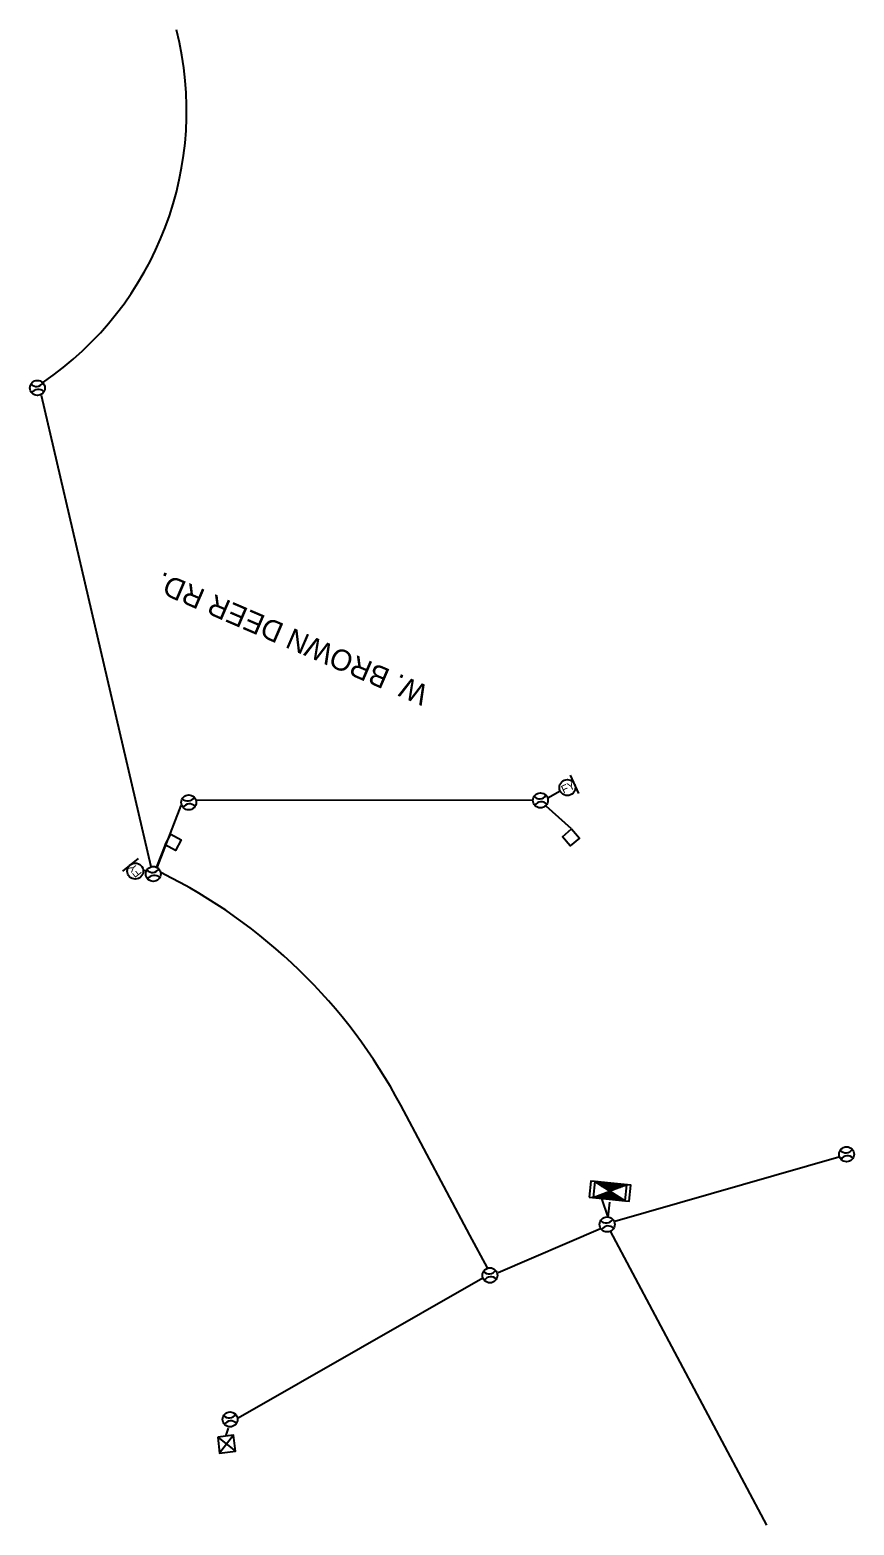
# Model space of a CAD drawing. Extents: x 601562 to 605316, y 332050 to 402250.
# Drawn here: x 603536 to 603948, y 349499 to 350247 of the extents above; entities that cross this region are included whole.
import ezdxf

# ---------------------------------------------------------------- set-up
doc = ezdxf.new("R2010")
doc.units = 0
doc.layers.add('P_FTMS', color=7, linetype='Continuous')
doc.layers.add('P_FTMSConduit', color=7, linetype='Continuous')

# ---------------------------------------------------------------- blocks, each defined once
blk = doc.blocks.new('FFY')
at = {"layer": 'P_FTMS'}
blk.add_line((24.4, -30.5), (24.4, 30.5), dxfattribs=at)
blk.add_circle((0, 0), 24.4, dxfattribs=at)
blk.add_text('FY', height=24.38, dxfattribs=at).set_placement((-18.5, -12.2))
blk = doc.blocks.new('FCB_2')
at = {"layer": 'P_FTMS'}
for p, q in [((-48.3, 24.1), (-48, 24.4)), ((-45.5, 22.7), (-47.1, 24.4)), ((-46.9, 23.4), (-46, 24.4)), ((-45.5, 22.8), (-43.9, 24.4)), ((-41.4, 20.7), (-45.1, 24.4)), ((-44.1, 22.1), (-41.8, 24.4)), ((-37.2, 18.6), (-43, 24.4)), ((-42.8, 21.4), (-39.8, 24.4)), ((-41.4, 20.7), (-37.7, 24.4)), ((-33.1, 16.5), (-40.9, 24.4)), ((-40, 20), (-35.6, 24.4)), ((-29, 14.5), (-38.9, 24.4)), ((-38.6, 19.3), (-33.6, 24.4)), ((-37.2, 18.6), (-31.5, 24.4)), ((-24.8, 12.4), (-36.8, 24.4)), ((-35.9, 17.9), (-29.4, 24.4)), ((-20.7, 10.3), (-34.7, 24.4)), ((-34.5, 17.2), (-27.3, 24.4)), ((-33.1, 16.5), (-25.3, 24.4)), ((-16.5, 8.3), (-32.7, 24.4)), ((-31.7, 15.9), (-23.2, 24.4)), ((-12.4, 6.2), (-30.6, 24.4)), ((-30.3, 15.2), (-21.1, 24.4)), ((-29, 14.5), (-19.1, 24.4)), ((-8.3, 4.1), (-28.5, 24.4)), ((-27.6, 13.8), (-17, 24.4)), ((-4.1, 2.1), (-26.4, 24.4)), ((-26.2, 13.1), (-14.9, 24.4)), ((-24.8, 12.4), (-12.9, 24.4)), ((0, 0), (-24.4, 24.4)), ((-24.4, -24.4), (0, 0)), ((-23.5, 11.7), (-10.8, 24.4)), ((1.4, 0.7), (-22.3, 24.4)), ((-22.1, 11), (-8.7, 24.4)), ((-20.7, 10.3), (-6.7, 24.4)), ((2.8, 1.4), (-20.2, 24.4)), ((-19.3, 9.7), (-4.6, 24.4)), ((4.1, 2.1), (-18.2, 24.4)), ((-17.9, 9), (-2.5, 24.4)), ((-16.6, 8.3), (-0.4, 24.4)), ((5.5, 2.8), (-16.1, 24.4)), ((-15.2, 7.6), (1.6, 24.4)), ((6.9, 3.4), (-14, 24.4)), ((-13.8, 6.9), (3.7, 24.4)), ((-12.4, 6.2), (5.8, 24.4)), ((8.3, 4.1), (-12, 24.4)), ((-11, 5.5), (7.8, 24.4)), ((9.7, 4.8), (-9.9, 24.4)), ((-9.7, 4.8), (9.9, 24.4)), ((-8.3, 4.1), (12, 24.4)), ((11, 5.5), (-7.8, 24.4)), ((-6.9, 3.4), (14, 24.4)), ((12.4, 6.2), (-5.8, 24.4)), ((-5.5, 2.8), (16.1, 24.4)), ((-4.1, 2.1), (18.2, 24.4)), ((13.8, 6.9), (-3.7, 24.4)), ((-2.8, 1.4), (20.2, 24.4)), ((15.2, 7.6), (-1.6, 24.4)), ((-1.4, 0.7), (22.3, 24.4)), ((0, 0), (24.4, 24.4)), ((24.4, -24.4), (0, 0)), ((16.6, 8.3), (0.4, 24.4)), ((17.9, 9), (2.5, 24.4)), ((4.1, 2.1), (26.5, 24.4)), ((19.3, 9.7), (4.6, 24.4)), ((20.7, 10.3), (6.7, 24.4)), ((8.3, 4.1), (28.5, 24.4)), ((22.1, 11), (8.7, 24.4)), ((23.4, 11.7), (10.8, 24.4)), ((12.4, 6.2), (30.6, 24.4)), ((24.8, 12.4), (12.9, 24.4)), ((26.2, 13.1), (14.9, 24.4)), ((16.6, 8.3), (32.7, 24.4)), ((27.6, 13.8), (17, 24.4)), ((29, 14.5), (19.1, 24.4)), ((20.7, 10.3), (34.7, 24.4)), ((30.3, 15.2), (21.1, 24.4)), ((31.7, 15.9), (23.2, 24.4)), ((24.8, 12.4), (36.8, 24.4)), ((33.1, 16.6), (25.3, 24.4)), ((34.5, 17.2), (27.3, 24.4)), ((29, 14.5), (38.9, 24.4)), ((35.9, 17.9), (29.4, 24.4)), ((37.2, 18.6), (31.5, 24.4)), ((33.1, 16.6), (40.9, 24.4)), ((38.6, 19.3), (33.5, 24.4)), ((40, 20), (35.6, 24.4)), ((37.2, 18.6), (43, 24.4)), ((41.4, 20.7), (37.7, 24.4)), ((42.8, 21.4), (39.8, 24.4)), ((41.4, 20.7), (45.1, 24.4)), ((44.1, 22.1), (41.8, 24.4)), ((45.5, 22.8), (43.9, 24.4)), ((45.5, 22.8), (47.1, 24.4)), ((46.9, 23.5), (46, 24.4)), ((48.3, 24.1), (48, 24.4)), ((-48, -24.4), (-48.3, -24.1)), ((-47.2, -24.4), (-45.5, -22.8)), ((-45.9, -24.4), (-46.9, -23.5)), ((-43.9, -24.4), (-45.5, -22.8)), ((-45.1, -24.4), (-41.4, -20.7)), ((-41.8, -24.4), (-44.1, -22.1)), ((-43, -24.4), (-37.3, -18.6)), ((-39.7, -24.4), (-42.8, -21.4)), ((-37.7, -24.4), (-41.4, -20.7)), ((-41, -24.4), (-33.1, -16.6)), ((-35.6, -24.4), (-40, -20)), ((-38.9, -24.4), (-29, -14.5)), ((-33.5, -24.4), (-38.6, -19.3)), ((-31.5, -24.4), (-37.2, -18.6)), ((-36.8, -24.4), (-24.8, -12.4)), ((-29.4, -24.4), (-35.9, -17.9)), ((-34.8, -24.4), (-20.7, -10.4)), ((-27.3, -24.4), (-34.5, -17.2)), ((-25.3, -24.4), (-33.1, -16.6)), ((-32.7, -24.4), (-16.6, -8.3)), ((-23.2, -24.4), (-31.7, -15.9)), ((-30.6, -24.4), (-12.4, -6.2)), ((-21.1, -24.4), (-30.3, -15.2)), ((-19, -24.4), (-29, -14.5)), ((-28.5, -24.4), (-8.3, -4.1)), ((-17, -24.4), (-27.6, -13.8)), ((-26.5, -24.4), (-4.1, -2.1)), ((-14.9, -24.4), (-26.2, -13.1)), ((-12.8, -24.4), (-24.8, -12.4)), ((-10.8, -24.4), (-23.4, -11.7)), ((-22.3, -24.4), (1.4, -0.7)), ((-8.7, -24.4), (-22.1, -11)), ((-6.6, -24.4), (-20.7, -10.3)), ((-20.3, -24.4), (2.8, -1.4)), ((-4.6, -24.4), (-19.3, -9.7)), ((-18.2, -24.4), (4.1, -2.1)), ((-2.5, -24.4), (-17.9, -9)), ((-0.4, -24.4), (-16.6, -8.3)), ((-16.1, -24.4), (5.5, -2.8)), ((1.6, -24.4), (-15.2, -7.6)), ((-14.1, -24.4), (6.9, -3.4)), ((3.7, -24.4), (-13.8, -6.9)), ((5.8, -24.4), (-12.4, -6.2)), ((-12, -24.4), (8.3, -4.1)), ((7.8, -24.4), (-11, -5.5)), ((-9.9, -24.4), (9.7, -4.8)), ((9.9, -24.4), (-9.7, -4.8)), ((12, -24.4), (-8.3, -4.1)), ((-7.8, -24.4), (11, -5.5)), ((14.1, -24.4), (-6.9, -3.5)), ((-5.8, -24.4), (12.4, -6.2)), ((16.1, -24.4), (-5.5, -2.8)), ((18.2, -24.4), (-4.1, -2.1)), ((-3.7, -24.4), (13.8, -6.9)), ((20.3, -24.4), (-2.8, -1.4)), ((-1.6, -24.4), (15.2, -7.6)), ((22.3, -24.4), (-1.4, -0.7)), ((0.4, -24.4), (16.6, -8.3)), ((2.5, -24.4), (17.9, -9)), ((26.5, -24.4), (4.1, -2.1)), ((4.6, -24.4), (19.3, -9.7)), ((6.6, -24.4), (20.7, -10.3)), ((28.5, -24.4), (8.3, -4.1)), ((8.7, -24.4), (22.1, -11)), ((10.8, -24.4), (23.4, -11.7)), ((30.6, -24.4), (12.4, -6.2)), ((12.8, -24.4), (24.8, -12.4)), ((14.9, -24.4), (26.2, -13.1)), ((32.7, -24.4), (16.6, -8.3)), ((17, -24.4), (27.6, -13.8)), ((19.1, -24.4), (29, -14.5)), ((34.7, -24.4), (20.7, -10.3)), ((21.1, -24.4), (30.3, -15.2)), ((23.2, -24.4), (31.7, -15.9)), ((36.8, -24.4), (24.8, -12.4)), ((25.3, -24.4), (33.1, -16.6)), ((27.3, -24.4), (34.5, -17.2)), ((38.9, -24.4), (29, -14.5)), ((29.4, -24.4), (35.9, -17.9)), ((31.5, -24.4), (37.2, -18.6)), ((40.9, -24.4), (33.1, -16.6)), ((33.5, -24.4), (38.6, -19.3)), ((35.6, -24.4), (40, -20)), ((43, -24.4), (37.2, -18.6)), ((37.7, -24.4), (41.4, -20.7)), ((39.7, -24.4), (42.8, -21.4)), ((45.1, -24.4), (41.4, -20.7)), ((41.8, -24.4), (44.1, -22.1)), ((43.9, -24.4), (45.5, -22.8)), ((47.2, -24.4), (45.5, -22.8)), ((46, -24.4), (46.9, -23.5)), ((48, -24.4), (48.3, -24.1))]:
    blk.add_line(p, q, dxfattribs=at)
for points in [[(61, 24.4), (-61, 24.4), (-61, -24.4), (61, -24.4)], [(48.8, 24.4), (-48.8, 24.4), (-48.8, -24.4), (48.8, -24.4)], [(48.8, 24.4), (0, 0), (-48.8, 24.4)], [(48.8, -24.4), (-48.8, -24.4), (0, 0)]]:
    blk.add_lwpolyline(points, close=True, dxfattribs=at)
blk = doc.blocks.new('FMB_2')
at = {"layer": 'P_FTMS'}
for p, q in [((24.4, -24.4), (-24.4, 24.4)), ((-24.4, -24.4), (24.4, 24.4))]:
    blk.add_line(p, q, dxfattribs=at)
blk.add_lwpolyline([(24.4, -24.4), (24.4, 24.4), (-24.4, 24.4), (-24.4, -24.4)], close=True, dxfattribs=at)

msp = doc.modelspace()

# ---------------------------------------------------------------- linework, layer by layer
at = {"layer": 'P_FTMS'}
for p, q in [((603806.94, 349847.4), (603794.26, 349858.86)), ((603603.7, 349839.53), (603599.51, 349828.54))]:
    msp.add_line(p, q, dxfattribs=at)
for points in [[(603603.7, 349839.53), (603606.54, 349844.81), (603611.82, 349841.97), (603608.98, 349836.69), (603603.7, 349839.53)], [(603806.94, 349847.4), (603810.83, 349842.84), (603806.27, 349838.95), (603802.38, 349843.52), (603806.94, 349847.41)]]:
    msp.add_lwpolyline(points, dxfattribs=at)
for centre in [(603539.91, 350067.92), (603791.37, 349861.7), (603615.56, 349860.67), (603597.84, 349824.93), (603944.4, 349684.76), (603824.72, 349649.66), (603766.13, 349624.23), (603636.22, 349552.21)]:
    msp.add_circle(centre, 3.75, dxfattribs=at)
for centre, start, end in [((603539.47, 350072.39), 222.48308, 328.73873), ((603540.35, 350063.44), 42.48308, 148.73873), ((603615.12, 349865.15), 222.48308, 328.73873), ((603616, 349856.19), 42.48308, 148.73873), ((603790.93, 349866.18), 222.48308, 328.73873), ((603791.81, 349857.22), 42.48308, 148.73873), ((603597.4, 349829.41), 222.48308, 328.73873), ((603598.28, 349820.46), 42.48308, 148.73873), ((603943.96, 349689.24), 222.48308, 328.73873), ((603944.84, 349680.28), 42.48308, 148.73873), ((603824.28, 349654.14), 222.48308, 328.73873), ((603825.16, 349645.18), 42.48308, 148.73873), ((603765.69, 349628.71), 222.48308, 328.73873), ((603766.57, 349619.75), 42.48308, 148.73873), ((603635.78, 349556.69), 222.48308, 328.73873), ((603636.66, 349547.73), 42.48308, 148.73873)]:
    msp.add_arc(centre, 3.75, start, end, dxfattribs=at)
at = {"layer": 'P_FTMSConduit'}
for p, q in [((603541.77, 350064.35), (603596.64, 349828.61)), ((603795.08, 349863.02), (603801.18, 349866.43)), ((603611.69, 349859.09), (603599.7, 349828.45)), ((603619.22, 349861.77), (603787.4, 349862.03)), ((603594.37, 349826.56), (603592.84, 349826.49)), ((603756.1, 349644.32), (603721.54, 349709.29)), ((603828.54, 349651.3), (603940.57, 349683.41)), ((603825.15, 349653.39), (603822.09, 349662.68)), ((603825.15, 349653.39), (603825.99, 349660.77)), ((603764.83, 349627.92), (603756.1, 349644.32)), ((603770.19, 349625.59), (603821.46, 349647.71)), ((603904.5, 349499.36), (603826.33, 349646.27)), ((603640.35, 349552.99), (603762.65, 349622.91)), ((603634.04, 349543.79), (603635.36, 349547.78))]:
    msp.add_line(p, q, dxfattribs=at)
for centre, radius, start, end in [((603450.27, 350206.4), 164.22, 304.16509, 14.27969), ((603480.96, 349581.27), 272.51, 28.01789, 63.64737)]:
    msp.add_arc(centre, radius, start, end, dxfattribs=at)

# ---------------------------------------------------------------- block references
at = {"layer": 'P_FTMS'}
for name, p, xscale, yscale, rotation in [('FFY', (603804.82, 349868.08), 0.16404166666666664, 0.16404166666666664, 24.34862605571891), ('FFY', (603588.85, 349826.32), 0.16404166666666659, 0.16404166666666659, 128.24791319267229), ('FCB_2', (603826.13, 349666.3), 0.16404166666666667, 0.1640416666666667, 174.31033180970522), ('FMB_2', (603634.51, 349539.82), 0.16404166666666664, 0.1640416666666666, -173.22126124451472)]:
    msp.add_blockref(name, p, dxfattribs=dict(at, xscale=xscale, yscale=yscale, rotation=rotation))

# ---------------------------------------------------------------- texts
at = {"layer": 'P_FTMSConduit'}
msp.add_text('W. BROWN DEER RD.', height=10.5, rotation=156.70507, dxfattribs=at).set_placement((603736.2, 349918.5))

doc.saveas('drawing.dxf')
